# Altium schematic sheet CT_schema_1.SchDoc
size 451 x 355 mm
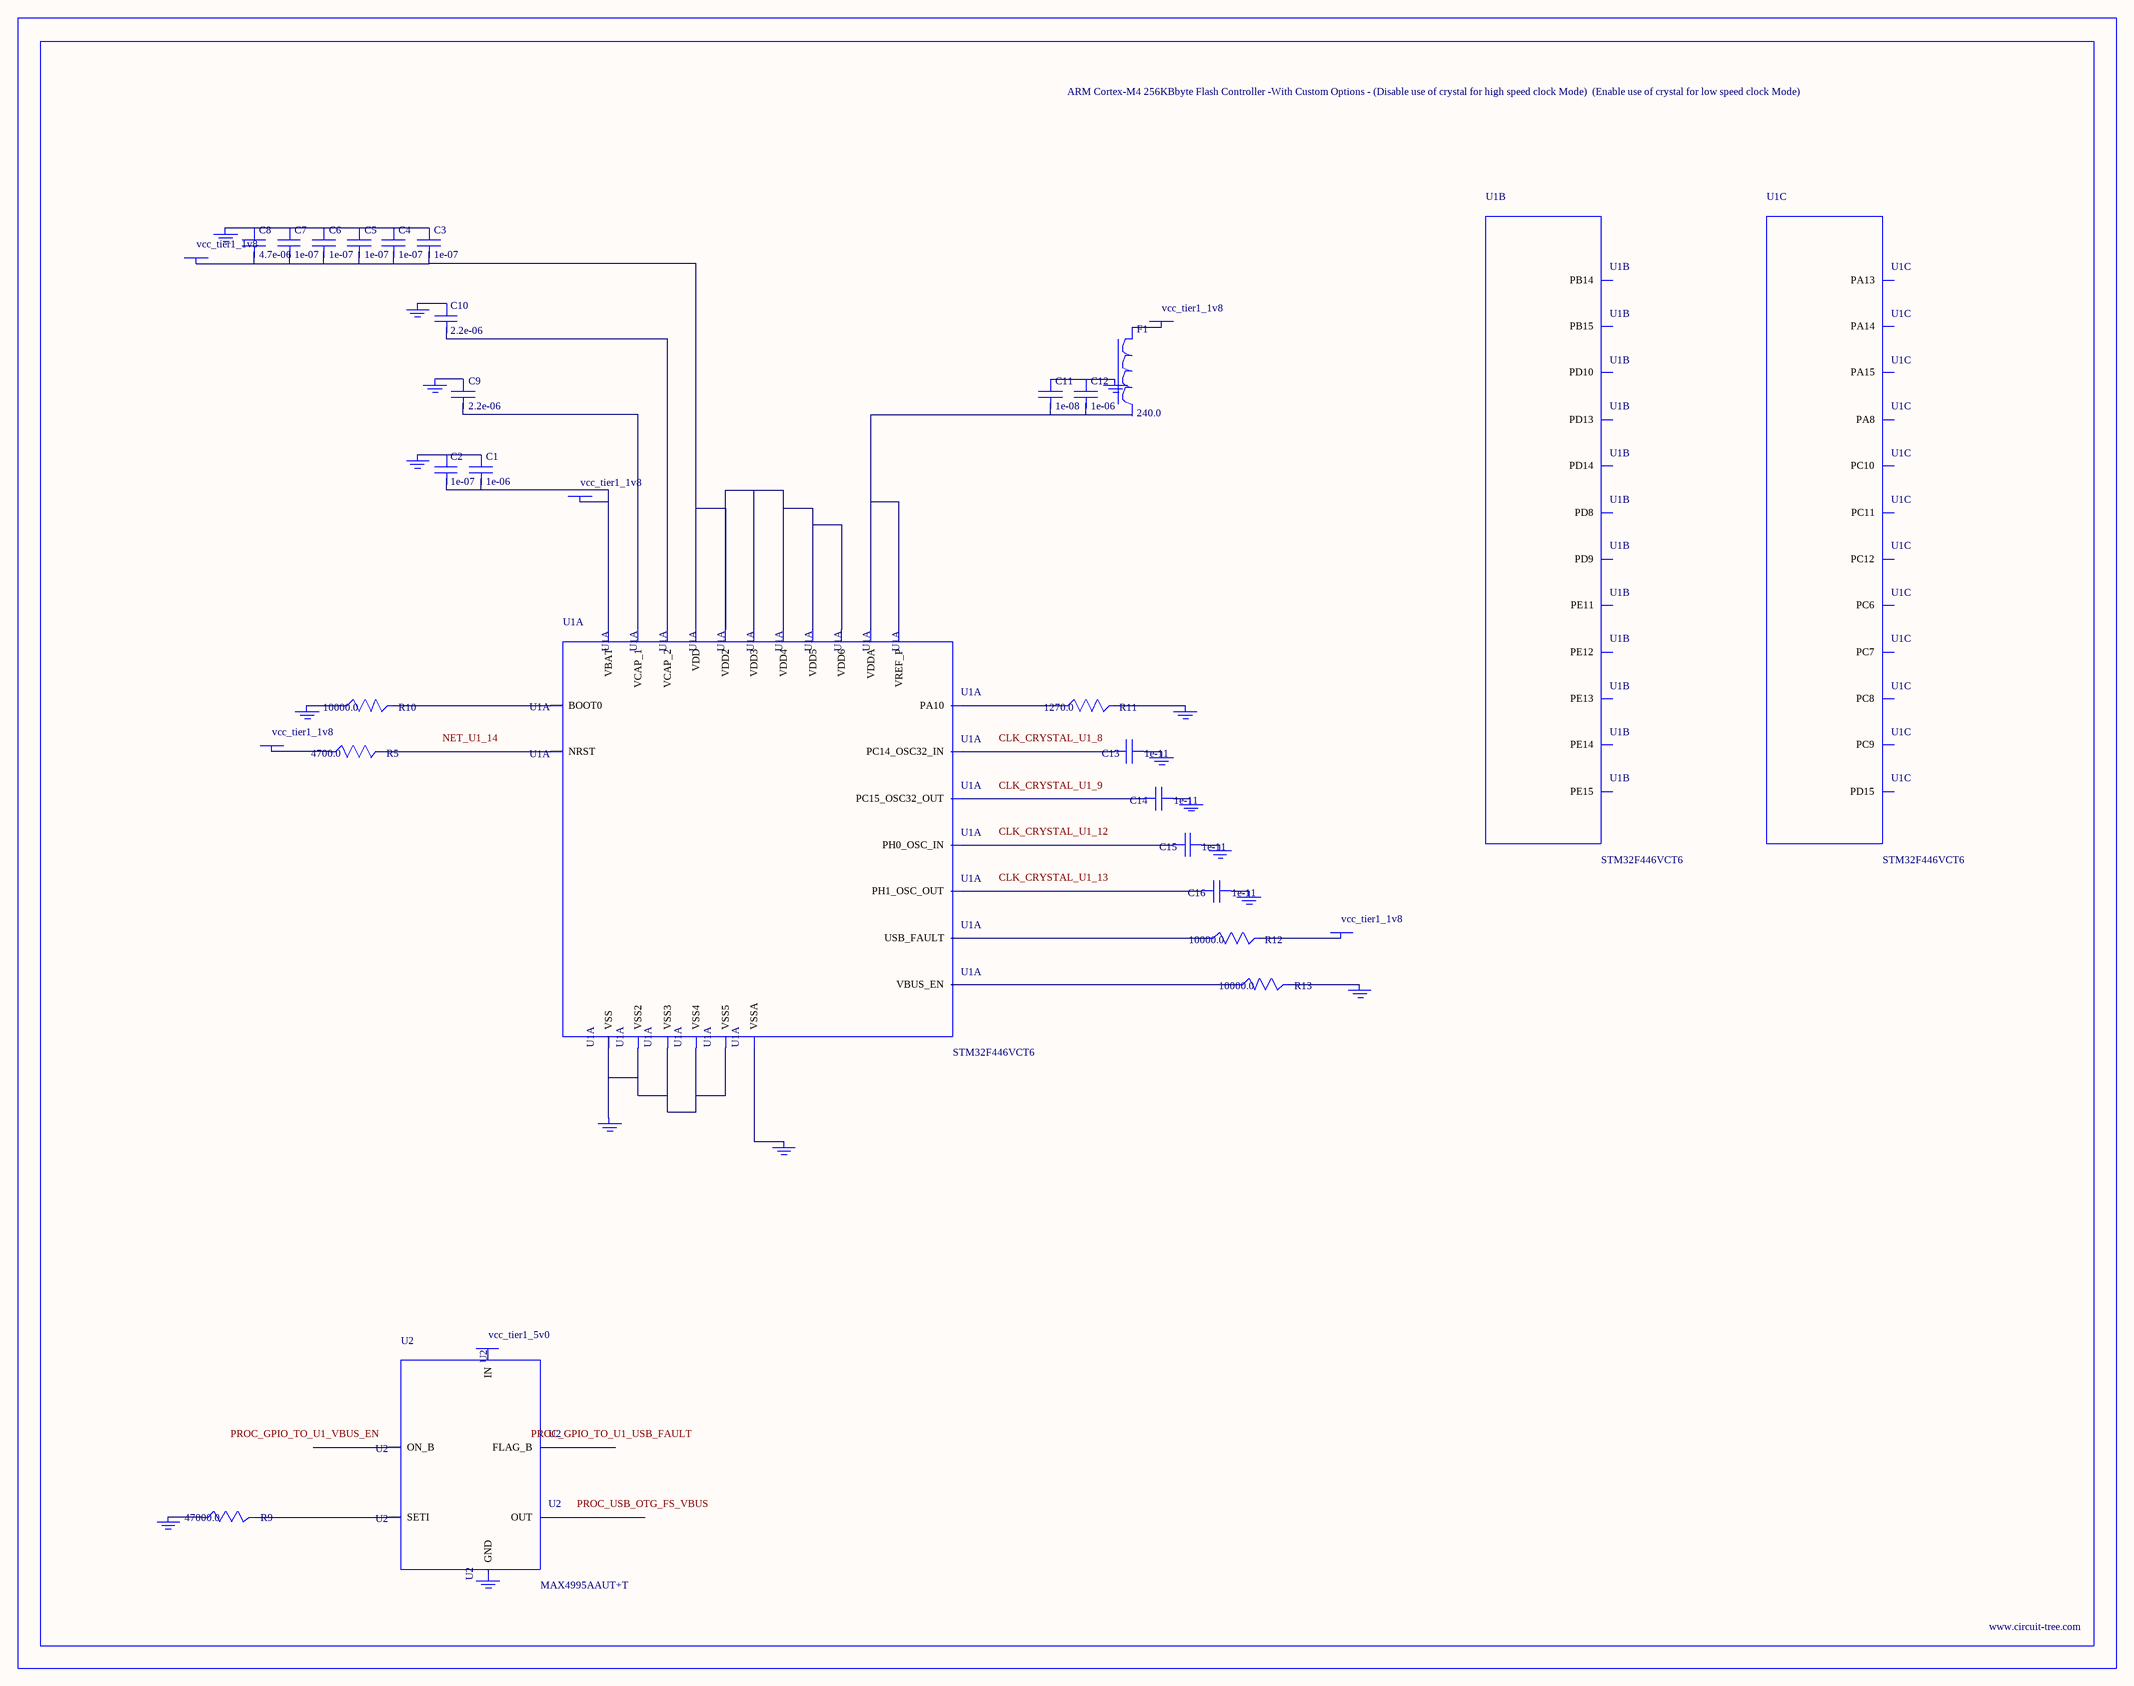
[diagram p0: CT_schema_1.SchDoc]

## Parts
BORDER0  (no value)
C1  1e-06  [C0603]
C2  1e-07  [C0603]
C3  1e-07  [C0603]
C4  1e-07  [C0603]
C5  1e-07  [C0603]
C6  1e-07  [C0603]
C7  1e-07  [C0603]
C8  4.7e-06  [C0603]
C9  2.2e-06  [C0603]
C10  2.2e-06  [C0603]
C11  1e-08  [C0603]
C12  1e-06  [C0603]
C13  1e-11  [C0402]
C14  1e-11  [C0402]
C15  1e-11  [C0402]
C16  1e-11  [C0402]
F1  240.0  [L0603]
GND_INSTANCE_0_0  (no value)
GND_INSTANCE_0_1  (no value)
GND_INSTANCE_0_2  (no value)
GND_INSTANCE_0_3  (no value)
GND_INSTANCE_0_4  (no value)
GND_INSTANCE_0_5  (no value)
GND_INSTANCE_0_6  (no value)
GND_INSTANCE_0_7  (no value)
GND_INSTANCE_0_8  (no value)
GND_INSTANCE_0_9  (no value)
GND_INSTANCE_0_10  (no value)
GND_INSTANCE_0_11  (no value)
GND_INSTANCE_0_12  (no value)
GND_INSTANCE_0_13  (no value)
GND_INSTANCE_0_14  (no value)
GND_INSTANCE_0_15  (no value)
POWER_INSTANCE_0_0  vcc_tier1_1v8
POWER_INSTANCE_0_1  vcc_tier1_1v8
POWER_INSTANCE_0_2  vcc_tier1_1v8
POWER_INSTANCE_0_3  vcc_tier1_1v8
POWER_INSTANCE_0_4  vcc_tier1_1v8
POWER_INSTANCE_0_5  vcc_tier1_5v0
R5  4700.0  [R0603]
R9  47000.0  [R0603]
R10  10000.0  [R0603]
R11  1270.0  [R0603]
R12  10000.0  [R0603]
R13  10000.0  [R0603]
U1  STM32F446VCT6  [LQFP100]  (parts A,B,C of 9)
U2  MAX4995AAUT+T  [SOT-23-6]

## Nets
NetC1_1: C1.1 C2.1 GND_INSTANCE_0_1.0(GND)
NetC1_2: C1.2 C2.2 POWER_INSTANCE_0_1.0(PWR) U1.6(VBAT)
NetC3_1: C3.1 C4.1 C5.1 C6.1 C7.1 C8.1 GND_INSTANCE_0_4.0(GND)
NetC3_2: C3.2 C4.2 C5.2 C6.2 C7.2 C8.2 POWER_INSTANCE_0_2.0(PWR) U1.11(VDD) U1.19(VDD2) U1.28(VDD3) U1.50(VDD4) U1.75(VDD5) U1.100(VDD6)
NetC9_1: C9.1 GND_INSTANCE_0_9.0(GND)
NetC9_2: C9.2 U1.48(VCAP_1)
NetC10_1: C10.1 GND_INSTANCE_0_11.0(GND)
NetC10_2: C10.2 U1.73(VCAP_2)
NetC11_1: C11.1 C12.1 GND_INSTANCE_0_8.0(GND)
NetC11_2: C11.2 C12.2 U1.21(VREF_P) U1.22(VDDA)
NetC13_1: C13.1 GND_INSTANCE_0_2.0(GND)
NetC13_2: C13.2 U1.8(PC14_OSC32_IN)
NetC14_1: C14.1 GND_INSTANCE_0_3.0(GND)
NetC14_2: C14.2 U1.9(PC15_OSC32_OUT)
NetC15_1: C15.1 GND_INSTANCE_0_5.0(GND)
NetC15_2: C15.2 U1.12(PH0_OSC_IN)
NetC16_1: C16.1 GND_INSTANCE_0_6.0(GND)
NetC16_2: C16.2 U1.13(PH1_OSC_OUT)
NetF1_1: F1.1 POWER_INSTANCE_0_3.0(PWR)
NetGND_INSTANCE_0_0_0: GND_INSTANCE_0_0.0(GND) R13.2
NetGND_INSTANCE_0_7_0: GND_INSTANCE_0_7.0(GND) U1.20(VSSA)
NetGND_INSTANCE_0_10_0: GND_INSTANCE_0_10.0(GND) R11.2
NetGND_INSTANCE_0_12_0: GND_INSTANCE_0_12.0(GND) R10.1
NetGND_INSTANCE_0_13_0: GND_INSTANCE_0_13.0(GND) U1.10(VSS) U1.27(VSS2) U1.49(VSS3) U1.74(VSS4) U1.99(VSS5)
NetGND_INSTANCE_0_14_0: GND_INSTANCE_0_14.0(GND) R9.1
NetPOWER_INSTANCE_0_0_0: POWER_INSTANCE_0_0.0(PWR) R12.2
NetPOWER_INSTANCE_0_4_0: POWER_INSTANCE_0_4.0(PWR) R5.1
NetR5_2: R5.2 U1.14(NRST)
NetR9_2: R9.2 U2.3(SETI)
NetR10_2: R10.2 U1.94(BOOT0)
NetR11_1: R11.1 U1.69(PA10)
NetR12_1: R12.1 U1.3(USB_FAULT)
NetR13_1: R13.1 U1.2(VBUS_EN)

Not connected (* = marked no-connect by the designer): F1 2; GND_INSTANCE_0_15 0(GND); POWER_INSTANCE_0_5 0(PWR); U1 42(PE11) 43(PE12) 44(PE13) 45(PE14) 46(PE15) 53(PB14) 54(PB15) 55(PD8) 56(PD9) 57(PD10) 60(PD13) 61(PD14) 62(PD15) 63(PC6) 64(PC7) 65(PC8) 66(PC9) 67(PA8) 72(PA13) 76(PA14) 77(PA15) 78(PC10) 79(PC11) 80(PC12); U2 1(OUT) 2(GND) 4(ON_B) 5(IN) 6(FLAG_B)

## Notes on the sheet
- Labels drawn without touching a wire or pin: CLK_CRYSTAL_U1_8, CLK_CRYSTAL_U1_9, CLK_CRYSTAL_U1_12, CLK_CRYSTAL_U1_13, NET_U1_14, PROC_GPIO_TO_U1_USB_FAULT, PROC_GPIO_TO_U1_VBUS_EN, PROC_USB_OTG_FS_VBUS

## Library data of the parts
BORDER0 = BORDER_PAGE0
C1 C12 = C0603C105K3RACTU
C2-C7 = 06035C104K4Z2A
C8 = GRM188R6YA475KE15D
C9 C10 = C0603C225K8RACTU
C11 = 06035C103K4Z2A
C13-C16 = C0402C100K3GACTU
F1 = Z0603C241ASMST
GND_INSTANCE_0_0-GND_INSTANCE_0_15 = GND
POWER_INSTANCE_0_0-POWER_INSTANCE_0_5 = PWR
R5 = RC0603JR-074K7L
R9 = RC0603JR-0747KL
R10 R12 R13 = RC0603JR-0710KL
R11 = RC0603FR-071K27L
